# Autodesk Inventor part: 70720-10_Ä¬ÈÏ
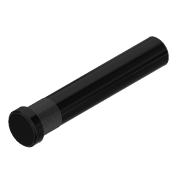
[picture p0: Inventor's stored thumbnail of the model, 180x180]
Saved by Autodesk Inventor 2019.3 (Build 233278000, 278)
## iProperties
Created: 2010-06
Part Number: 70720-10_Ä¬ÈÏ
Material: Ogólny
Document SubType Name: Modeling
Designer: CADENGINEERING4
Density: 1 g/cm^3
Appearance: Gładki — czarny
Author: CADENGINEERING4
Revision Number: ÈÎºÎ
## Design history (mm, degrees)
feature "NONE"
node "Bryła1"
